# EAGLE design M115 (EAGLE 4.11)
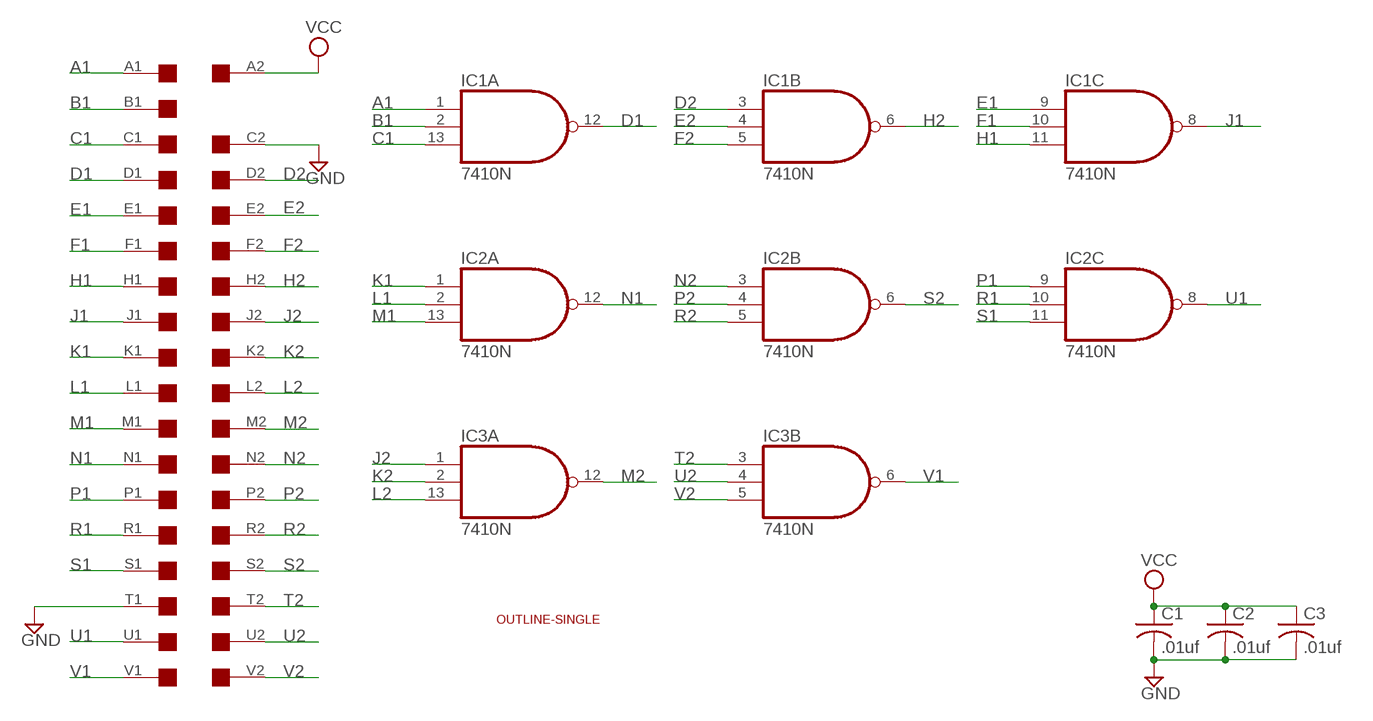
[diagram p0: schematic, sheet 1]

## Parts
C1  .01uf  C-US050-025X075  [C050-025X075]
C2  .01uf  C-US050-025X075  [C050-025X075]
C3  .01uf  C-US050-025X075  [C050-025X075]
IC1  7410N  [DIL14]
IC2  7410N  [DIL14]
IC3  7410N  [DIL14]
U$1  SINGLE  [EDGE-CON2]
U$4  OUTLINE-SINGLE  [SINGLE]

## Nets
A1: IC1.1(A:I0) U$1.A1
B1: IC1.2(A:I1) U$1.B1
C1: IC1.13(A:I2) U$1.C1
D1: IC1.12(A:O) U$1.D1
D2: IC1.3(B:I0) U$1.D2
E1: IC1.9(C:I0) U$1.E1
E2: IC1.4(B:I1) U$1.E2
F1: IC1.10(C:I1) U$1.F1
F2: IC1.5(B:I2) U$1.F2
GND: C1.2 C2.2 C3.2 U$1.C2 U$1.T1
H1: IC1.11(C:I2) U$1.H1
H2: IC1.6(B:O) U$1.H2
J1: IC1.8(C:O) U$1.J1
J2: IC3.1(A:I0) U$1.J2
K1: IC2.1(A:I0) U$1.K1
K2: IC3.2(A:I1) U$1.K2
L1: IC2.2(A:I1) U$1.L1
L2: IC3.13(A:I2) U$1.L2
M1: IC2.13(A:I2) U$1.M1
M2: IC3.12(A:O) U$1.M2
N1: IC2.12(A:O) U$1.N1
N2: IC2.3(B:I0) U$1.N2
P1: IC2.9(C:I0) U$1.P1
P2: IC2.4(B:I1) U$1.P2
R1: IC2.10(C:I1) U$1.R1
R2: IC2.5(B:I2) U$1.R2
S1: IC2.11(C:I2) U$1.S1
S2: IC2.6(B:O) U$1.S2
T2: IC3.3(B:I0) U$1.T2
U1: IC2.8(C:O) U$1.U1
U2: IC3.4(B:I1) U$1.U2
V1: IC3.6(B:O) U$1.V1
V2: IC3.5(B:I2) U$1.V2
VCC: C1.1 C2.1 C3.1 U$1.A2
Unconnected: IC3.8(C:O) IC3.9(C:I0) IC3.10(C:I1) IC3.11(C:I2) U$1.B2

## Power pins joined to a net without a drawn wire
GND: IC1.7(P:GND) IC2.7(P:GND) IC3.7(P:GND)
VCC: IC1.14(P:VCC) IC2.14(P:VCC) IC3.14(P:VCC)

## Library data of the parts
C1-C3 = rcl:C-US: CAPACITOR, American symbol
IC1-IC3 = 74xx-us:74*10: Triple 3-input NAND gate
U$1 = dec-con:SINGLE: Single-Height DEC board
U$4 = dec-con:OUTLINE-*: Board outlines for DEC boards.

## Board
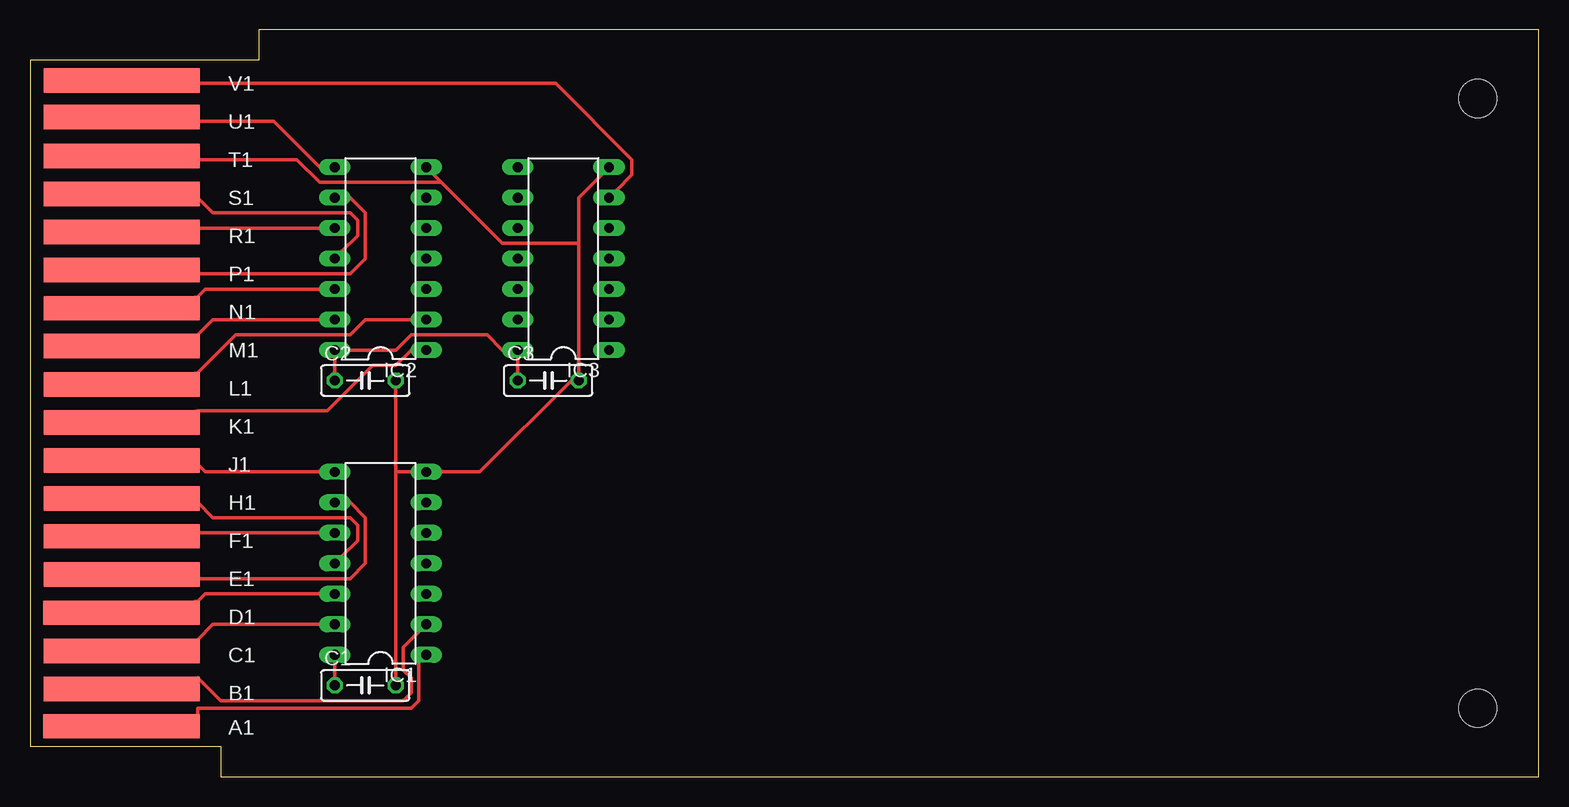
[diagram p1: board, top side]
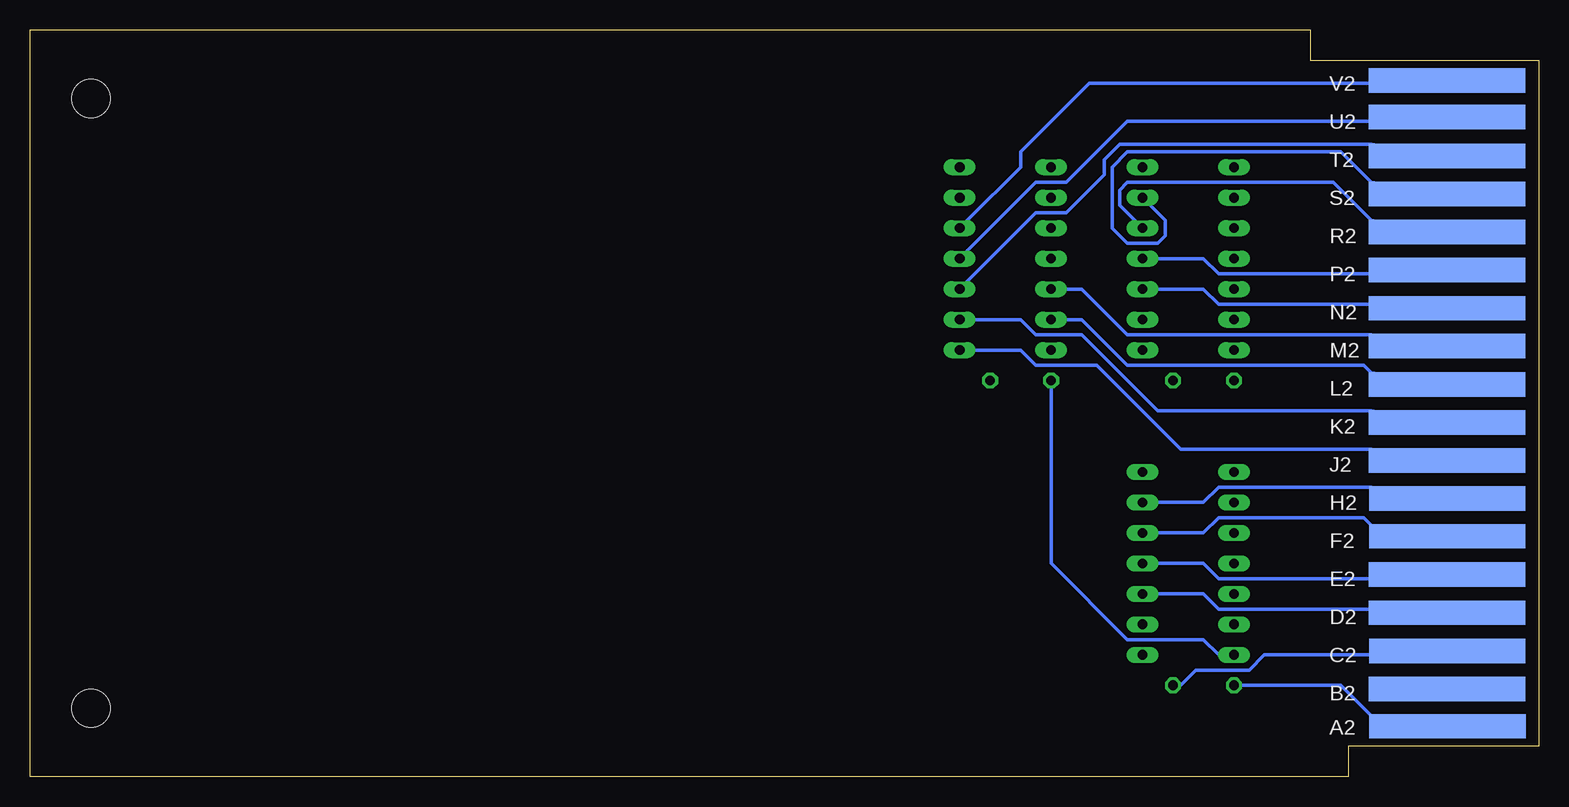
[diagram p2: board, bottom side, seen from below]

Size 125.73 x 62.23 mm. Coordinates in mm from the lower left corner, seen from the top.
Copper layers (1*16): Top 0.035mm / dielectric 1.5mm / Bottom 0.035mm
Design rules "10mils": minimum track width 12mil, minimum drill 28mil, track to track 10mil, track to pad 10mil, pad to pad 10mil, via to via 10mil, smd to smd 10mil, copper to edge 25mil, drill to drill 10mil, minimum pad ring 10mil, minimum via ring 8mil, stop-mask expansion 0mil, vias tented up to drill 0mil, thermal gap 10mil

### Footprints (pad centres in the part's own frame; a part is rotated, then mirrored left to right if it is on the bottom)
C050-025X075 = drill 0.813 octagon: 1 -2.54,0; 2 2.54,0
DIL14 = drill 0.813 long: 1 -7.62,-3.81; 2 -5.08,-3.81; 3 -2.54,-3.81; 4 0,-3.81; 5 2.54,-3.81; 6 5.08,-3.81; 7 7.62,-3.81; 8 7.62,3.81; 9 5.08,3.81; 10 2.54,3.81; 11 0,3.81; 12 -2.54,3.81; 13 -5.08,3.81; 14 -7.62,3.81
EDGE-CON2 = smd 13.017 x 2.032: A1 7.633,4.207; B1 7.639,7.327; C1 7.636,10.489; D1 7.633,13.665; E1 7.642,16.84; F1 7.642,20.041; H1 7.642,23.19; J1 7.642,26.34; K1 7.642,29.515; L1 7.642,32.69; M1 7.642,35.89; N1 7.642,39.04; P1 7.642,42.24; R1 7.642,45.39; S1 7.642,48.565; T1 7.642,51.74; U1 7.642,54.966; V1 7.642,58.026 | smd 13.017 x 2.032 bottom: A2 7.614,4.207; B2 7.642,7.328; C2 7.617,10.49; D2 7.642,13.665; E2 7.642,16.84; F2 7.617,20.041; H2 7.617,23.19; J2 7.642,26.34; K2 7.642,29.515; L2 7.642,32.69; M2 7.642,35.89; N2 7.642,39.04; P2 7.642,42.24; R2 7.642,45.39; S2 7.642,48.565; T2 7.642,51.74; U2 7.642,54.966; V2 7.642,58.026
SINGLE = hole 3.175: 120.65,56.515; 120.65,5.715

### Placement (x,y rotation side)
C1  27.94,7.62 0 top
C2  27.94,33.02 0 top
C3  43.18,33.02 0 top
IC1  29.21,17.78 90 top
IC2  29.21,43.18 90 top
IC3  44.45,43.18 90 top
U$1  0,0 0 top
U$4  0,0 0 top

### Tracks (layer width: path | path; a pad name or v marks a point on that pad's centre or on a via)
A1
  Top 0.305: IC1.1 32.39,9.53 32.39,6.35 31.75,5.71 13.97,5.71 13.97,5.08 U$1.A1
B1
  Top 0.305: IC1.2 32.39,12.06 31.12,10.79 31.12,8.89 31.75,8.26 31.75,6.99 31.12,6.35 15.88,6.35 13.97,8.26 U$1.B1
C1
  Top 0.305: IC1.13 24.13,12.7 15.24,12.7 13.97,11.43 U$1.C1
D1
  Top 0.305: IC1.12 24.13,15.24 14.61,15.24 13.97,14.61 U$1.D1
D2
  Bottom 0.305: IC1.3 31.75,15.24 27.94,15.24 26.67,13.97 13.97,13.97 U$1.D2
E1
  Top 0.305: IC1.9 26.67,22.86 27.94,21.59 27.94,17.78 26.67,16.51 13.97,16.51 U$1.E1
E2
  Bottom 0.305: IC1.4 31.75,17.78 27.94,17.78 26.67,16.51 13.97,16.51 U$1.E2
F1
  Top 0.305: IC1.10 24.13,20.32 13.97,20.32 U$1.F1
F2
  Bottom 0.305: IC1.5 31.75,20.32 27.94,20.32 26.67,21.59 14.61,21.59 13.97,20.95 U$1.F2
GND
  Top 0.305: 30.48,25.4 30.48,32.38 C2.2 | 30.48,25.4 30.48,8.26 C1.2 | 30.48,25.4 31.75,25.4 IC1.7 34.29,25.4 37.47,25.4 45.09,33.02 C3.2 45.72,33.66 45.72,44.45 | 45.72,44.45 45.72,48.26 47.63,50.16 IC3.7 | 34.29,49.53 39.37,44.45 45.72,44.45 | 34.29,49.53 33.66,50.16 IC2.7 | 34.29,49.53 24.13,49.53 22.23,51.44 13.97,51.44 U$1.T1
  Bottom 0.305: C1.2 29.85,7.62 28.58,8.89 24.13,8.89 22.86,10.16 13.97,10.16 U$1.C2
H1
  Top 0.305: IC1.11 26.04,18.41 27.31,19.68 27.31,20.95 26.67,21.59 15.24,21.59 13.97,22.86 U$1.H1
H2
  Bottom 0.305: IC1.6 31.75,22.86 27.94,22.86 26.67,24.13 13.97,24.13 U$1.H2
J1
  Top 0.305: IC1.8 24.13,25.4 14.61,25.4 13.97,26.04 U$1.J1
J2
  Bottom 0.305: IC3.1 46.99,35.56 43.18,35.56 41.91,34.29 36.83,34.29 29.85,27.3 13.97,27.3 U$1.J2
K1
  Top 0.305: IC2.1 31.75,35.56 30.48,34.29 28.58,34.29 24.77,30.48 13.97,30.48 U$1.K1
K2
  Bottom 0.305: IC3.2 46.99,38.1 43.18,38.1 41.91,36.83 38.1,36.83 31.75,30.48 13.97,30.48 U$1.K2
L1
  Top 0.305: IC2.2 31.75,38.1 27.94,38.1 26.67,36.83 17.15,36.83 13.97,33.66 U$1.L1
L2
  Bottom 0.305: IC3.13 39.37,38.1 38.1,38.1 34.29,34.29 14.61,34.29 13.97,33.66 U$1.L2
M1
  Top 0.305: IC2.13 24.13,38.1 15.24,38.1 13.97,36.83 U$1.M1
M2
  Bottom 0.305: IC3.12 39.37,40.64 38.1,40.64 34.29,36.83 13.97,36.83 U$1.M2
N1
  Top 0.305: IC2.12 24.13,40.64 14.61,40.64 13.97,40.01 U$1.N1
N2
  Bottom 0.305: IC2.3 31.75,40.64 27.94,40.64 26.67,39.37 13.97,39.37 U$1.N2
P1
  Top 0.305: IC2.9 26.67,48.26 27.94,46.99 27.94,43.18 26.67,41.91 13.97,41.91 U$1.P1
P2
  Bottom 0.305: IC2.4 31.75,43.18 27.94,43.18 26.67,41.91 13.97,41.91 U$1.P2
R1
  Top 0.305: IC2.10 24.13,45.72 13.97,45.72 U$1.R1
R2
  Bottom 0.305: IC2.5 33.66,46.35 34.93,47.62 34.93,48.9 34.29,49.53 17.15,49.53 13.97,46.35 U$1.R2
S1
  Top 0.305: IC2.11 26.04,43.81 27.31,45.09 27.31,46.35 26.67,46.99 15.24,46.99 13.97,48.26 U$1.S1
S2
  Bottom 0.305: IC2.6 32.39,47.62 31.12,46.35 31.12,45.09 31.75,44.45 34.29,44.45 35.56,45.72 35.56,50.8 34.29,52.07 16.51,52.07 13.97,49.53 U$1.S2
T2
  Bottom 0.305: IC3.3 47.63,41.27 41.91,46.99 39.37,46.99 36.2,50.16 36.2,51.44 34.93,52.7 13.97,52.7 U$1.T2
U1
  Top 0.305: IC2.8 24.13,50.8 20.32,54.61 13.97,54.61 U$1.U1
U2
  Bottom 0.305: IC3.4 47.63,43.81 41.91,49.53 39.37,49.53 34.29,54.61 13.97,54.61 U$1.U2
V1
  Top 0.305: IC3.6 48.9,48.9 50.17,50.16 50.17,51.44 43.82,57.78 13.97,57.78 U$1.V1
V2
  Bottom 0.305: IC3.5 47.63,46.35 43.18,50.8 43.18,52.07 37.47,57.78 13.97,57.78 U$1.V2
VCC
  Top 0.305: C2.1 25.4,33.66 25.4,34.92 IC2.14 26.67,35.56 30.48,35.56 31.75,36.83 38.1,36.83 39.37,35.56 IC3.14 40.64,34.92 40.64,33.66 C3.1 | C1.1 25.4,8.26 25.4,9.53 IC1.14
  Bottom 0.305: C1.1 24.77,7.62 16.51,7.62 14.61,5.71 13.97,5.08 U$1.A2 | C3.1 40.64,32.38 40.64,17.78 34.29,11.43 27.94,11.43 26.67,10.16 IC1.14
